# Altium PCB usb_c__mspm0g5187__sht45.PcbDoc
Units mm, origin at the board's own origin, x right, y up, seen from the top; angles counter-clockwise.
Board outline 68 x 40 mm, 2 copper layers (Top, Bottom), stack 0 mm thick; 35 components, 31 nets, 176 pads, 52 vias.
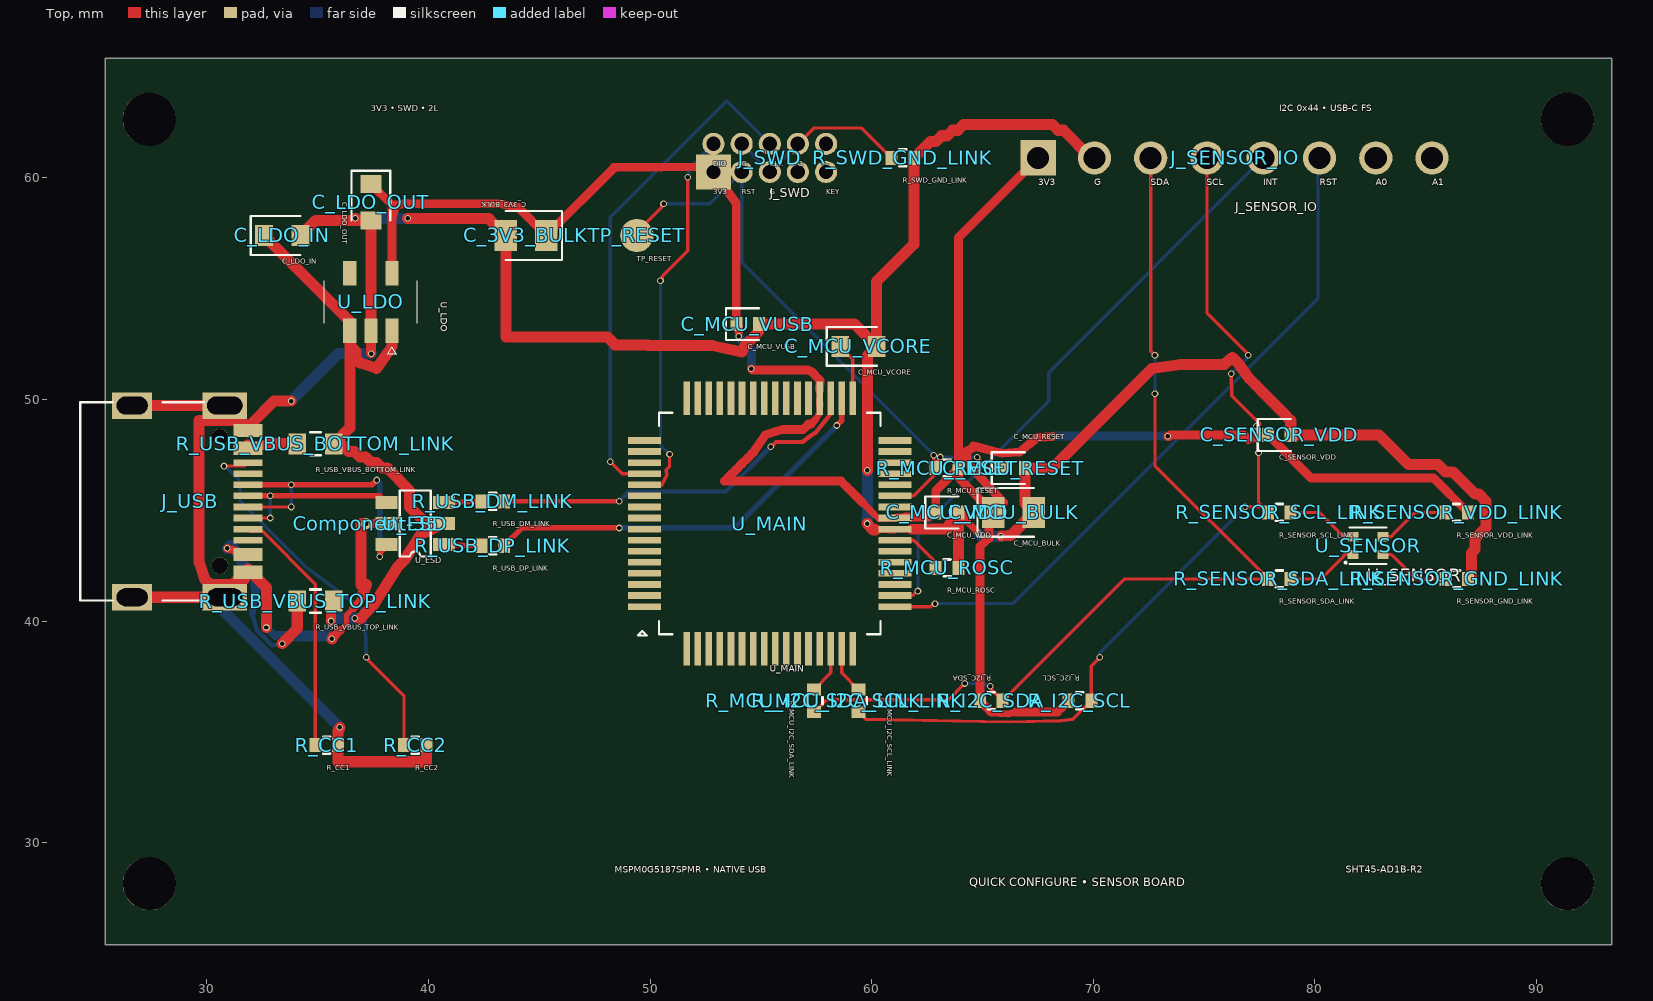
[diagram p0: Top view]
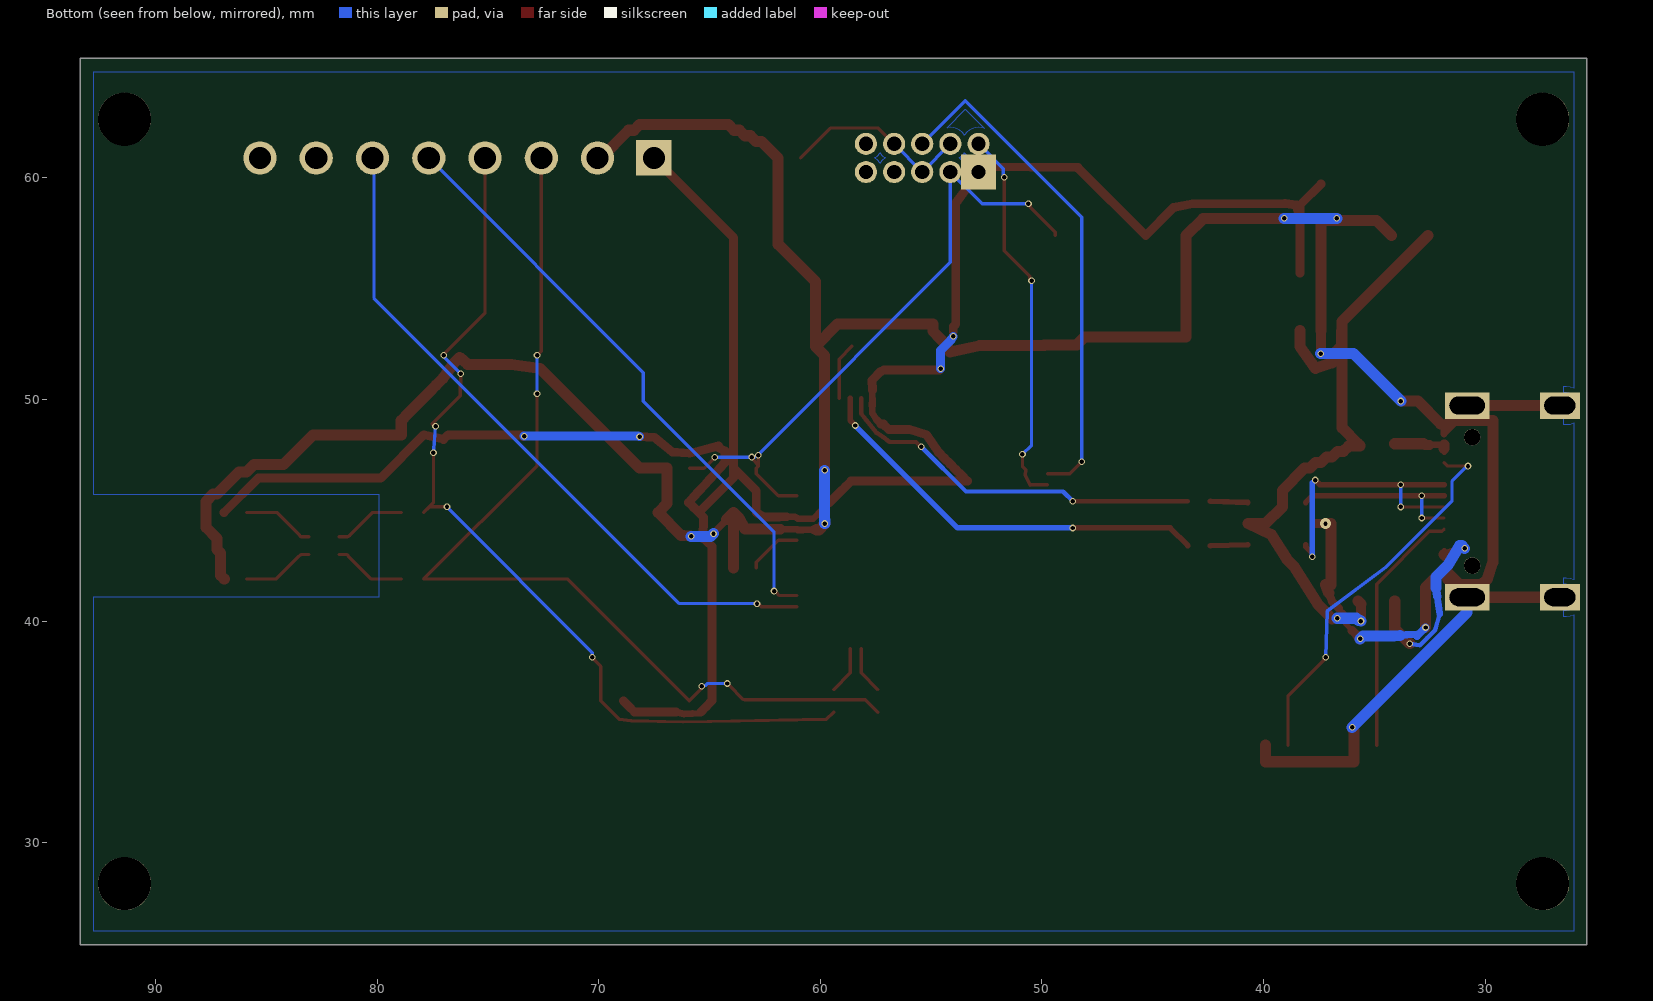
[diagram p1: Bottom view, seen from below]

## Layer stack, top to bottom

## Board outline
25.4,65.4 93.4,65.4 93.4,25.4 25.4,25.4

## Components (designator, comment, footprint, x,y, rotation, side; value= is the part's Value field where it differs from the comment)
C_3V3_BULK "" TSCIRCUIT-2.8500x1.4000mm 44.4,57.4 r180 top
C_LDO_IN "" TSCIRCUIT-2.4500x0.9500mm 33.4,57.4 r0 top
C_LDO_OUT "" TSCIRCUIT-0.9500x2.4500mm 37.4,58.9 r270 top
C_MCU_BULK "" TSCIRCUIT-2.8500x1.4000mm 66.4,44.9 r0 top
C_MCU_RESET "" TSCIRCUIT-1.5600x0.6400mm 66.4,46.9 r0 top
C_MCU_VCORE "" TSCIRCUIT-2.4500x0.9500mm 59.4,52.4 r0 top
C_MCU_VDD "" TSCIRCUIT-1.5600x0.6400mm 63.4,44.9 r0 top
C_MCU_VUSB "" TSCIRCUIT-1.5600x0.6400mm 54.4,53.4 r0 top
C_SENSOR_VDD "" TSCIRCUIT-1.5600x0.6400mm 78.4,48.4 r0 top
Component-35 "" TSCIRCUIT-0.5000x0.5000mm 37.2,44.4 r0 top
J_SENSOR_IO "" TSCIRCUIT-19.2800x1.5000mm 76.4,60.9 r0 top
J_SWD "" TSCIRCUIT-6.0800x2.2700mm 55.4,60.9 r0 top
J_USB "" TSCIRCUIT-6.7732x9.8502mm 29.112,45.4 r90 top
R_CC1 "" TSCIRCUIT-1.5600x0.6400mm 35.4,34.4 r0 top
R_CC2 "" TSCIRCUIT-1.5600x0.6400mm 39.4,34.4 r0 top
R_I2C_SCL "" TSCIRCUIT-1.5600x0.6400mm 69.4,36.4 r180 top
R_I2C_SDA "" TSCIRCUIT-1.5600x0.6400mm 65.4,36.4 r180 top
R_MCU_I2C_SCL_LINK "" TSCIRCUIT-0.6400x1.5600mm 59.4,36.4 r270 top
R_MCU_I2C_SDA_LINK "" TSCIRCUIT-0.6400x1.5600mm 57.4,36.4 r270 top
R_MCU_RESET "" TSCIRCUIT-1.5600x0.6400mm 63.4,46.9 r0 top
R_MCU_ROSC "" TSCIRCUIT-1.5600x0.6400mm 63.4,42.4 r0 top
R_SENSOR_GND_LINK "" TSCIRCUIT-1.5600x0.6400mm 86.4,41.9 r0 top
R_SENSOR_SCL_LINK "" TSCIRCUIT-1.5600x0.6400mm 78.4,44.9 r0 top
R_SENSOR_SDA_LINK "" TSCIRCUIT-1.5600x0.6400mm 78.4,41.9 r0 top
R_SENSOR_VDD_LINK "" TSCIRCUIT-1.5600x0.6400mm 86.4,44.9 r0 top
R_SWD_GND_LINK "" TSCIRCUIT-1.5600x0.6400mm 61.4,60.9 r0 top
R_USB_DM_LINK "" TSCIRCUIT-1.5600x0.6400mm 42.9,45.4 r0 top
R_USB_DP_LINK "" TSCIRCUIT-1.5600x0.6400mm 42.9,43.4 r0 top
R_USB_VBUS_BOTTOM_LINK "" TSCIRCUIT-2.4500x0.9500mm 34.9,48 r0 top
R_USB_VBUS_TOP_LINK "" TSCIRCUIT-2.4500x0.9500mm 34.9,40.9 r0 top
TP_RESET "" TSCIRCUIT-1.5000x1.5000mm 49.4,57.4 r0 top
U_ESD "" TSCIRCUIT-3.6000x2.5000mm 39.4,44.4 r0 top
U_LDO "" TSCIRCUIT-2.5000x3.7000mm 37.4,54.4 r270 top
U_MAIN "" TSCIRCUIT-12.8000x12.8000mm 55.4,44.4 r0 top
U_SENSOR "" TSCIRCUIT-1.8598x1.2201mm 82.4,43.4 r0 top

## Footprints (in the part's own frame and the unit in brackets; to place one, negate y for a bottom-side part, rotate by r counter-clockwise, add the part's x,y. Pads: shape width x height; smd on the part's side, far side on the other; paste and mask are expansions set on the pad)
TSCIRCUIT-0.5000x0.5000mm [mm]
TSCIRCUIT-0.6400x1.5600mm [mm]
  rect 0.54x0.64 smd: 1(-0.51,0) 2(0.51,0)
  silkscreen extent -0.15,-0.38 0.15,0.38
TSCIRCUIT-0.9500x2.4500mm [mm]
  rect 0.8x0.95 smd: 1(-0.825,0) 2(0.825,0)
  silkscreen extent -1.43,-0.87 0.82,0.88
TSCIRCUIT-1.5000x1.5000mm [mm]
  round 1.5 smd: 1(0,0)
TSCIRCUIT-1.5600x0.6400mm [mm]
  rect 0.54x0.64 smd: 1(-0.51,0) 2(0.51,0)
  silkscreen extent -0.98,-0.72 0.51,0.72
TSCIRCUIT-1.8598x1.2201mm [mm]
  rect 0.505x0.42 smd: 1(-0.677,-0.4) 2(-0.677,0.4) 3(0.677,0.4) 4(0.677,-0.4)
  silkscreen extent -1.05,-0.83 0.83,0.83
TSCIRCUIT-2.4500x0.9500mm [mm]
  rect 0.8x0.95 smd: 1(-0.825,0) 2(0.825,0)
  silkscreen extent -1.42,-0.87 0.82,0.87
TSCIRCUIT-2.5000x3.7000mm [mm]
  rect 1.1x0.6 smd: 1(1.3,0.95) 2(1.3,0) 3(1.3,-0.95) 4(-1.3,-0.95) 5(-1.3,0.95)
  silkscreen extent -0.95,-2.1 2.35,2.1
TSCIRCUIT-2.8500x1.4000mm [mm]
  rect 1.025x1.4 smd: 1(-0.913,0) 2(0.913,0)
  silkscreen extent -1.63,-1.1 0.91,1.1
TSCIRCUIT-3.6000x2.5000mm [mm]
  rect 1x0.6 smd: 1(-1.3,-0.95) 2(-1.3,0) 3(-1.3,0.95) 4(1.3,0.95) 5(1.3,0) 6(1.3,-0.95)
  silkscreen extent -0.7,-1.49 0.7,1.49
TSCIRCUIT-6.0800x2.2700mm [mm]
  rect 1.6x1.6 hole 0.65: 1(-2.54,-0.635)
  round 1 hole 0.65: 2(-2.54,0.635) 3(-1.27,0.635) 4(0,0.635) 5(1.27,0.635) 6(2.54,0.635) 7(2.54,-0.635) 8(1.27,-0.635) 9(0,-0.635) 10(-1.27,-0.635)
TSCIRCUIT-6.7732x9.8502mm [mm]
  rect 0.3x1.3 smd: 1(-3.35,-2.737) 2(-3.05,-2.737) 3(-2.55,-2.737) 4(-2.25,-2.737) 5(-1.75,-2.737) 6(-1.25,-2.737) 7(-0.75,-2.737) 8(-0.25,-2.737) 9(0.25,-2.737) 10(0.75,-2.737) 11(1.25,-2.737) 12(1.75,-2.737) 13(2.55,-2.737) 14(2.25,-2.737) 15(3.35,-2.737) 16(3.05,-2.737)
  rect 1.2x2 hole 0.8 slot 1.6 at 90 deg: 17(-4.325,-1.693) 18(4.325,-1.693)
  rect 1.2x1.8 hole 0.8 slot 1.4 at 90 deg: 19(4.325,2.487) 20(-4.325,2.487)
  round 0.75 hole 0.75 unplated: NPTH-1(-2.9,-1.468) NPTH-2(2.9,-1.468)
  silkscreen extent -4.47,-0.75 4.47,4.83
TSCIRCUIT-12.8000x12.8000mm [mm]
  rect 1.5x0.3 smd: 1(-5.65,-3.75) 2(-5.65,-3.25) 3(-5.65,-2.75) 4(-5.65,-2.25) 5(-5.65,-1.75) 6(-5.65,-1.25) 7(-5.65,-0.75) 8(-5.65,-0.25) 9(-5.65,0.25) 10(-5.65,0.75) 11(-5.65,1.25) 12(-5.65,1.75) 13(-5.65,2.25) 14(-5.65,2.75) 15(-5.65,3.25) 16(-5.65,3.75) 33(5.65,3.75) 34(5.65,3.25) 35(5.65,2.75) 36(5.65,2.25) 37(5.65,1.75) 38(5.65,1.25) 39(5.65,0.75) 40(5.65,0.25) 41(5.65,-0.25) 42(5.65,-0.75) 43(5.65,-1.25) 44(5.65,-1.75) 45(5.65,-2.25) 46(5.65,-2.75) 47(5.65,-3.25) 48(5.65,-3.75)
  rect 0.3x1.5 smd: 17(-3.75,5.65) 18(-3.25,5.65) 19(-2.75,5.65) 20(-2.25,5.65) 21(-1.75,5.65) 22(-1.25,5.65) 23(-0.75,5.65) 24(-0.25,5.65) 25(0.25,5.65) 26(0.75,5.65) 27(1.25,5.65) 28(1.75,5.65) 29(2.25,5.65) 30(2.75,5.65) 31(3.25,5.65) 32(3.75,5.65) 49(3.75,-5.65) 50(3.25,-5.65) 51(2.75,-5.65) 52(2.25,-5.65) 53(1.75,-5.65) 54(1.25,-5.65) 55(0.75,-5.65) 56(0.25,-5.65) 57(-0.25,-5.65) 58(-0.75,-5.65) 59(-1.25,-5.65) 60(-1.75,-5.65) 61(-2.25,-5.65) 62(-2.75,-5.65) 63(-3.25,-5.65) 64(-3.75,-5.65)
  silkscreen extent -5.95,-5.05 5,5
TSCIRCUIT-19.2800x1.5000mm [mm]
  rect 1.6x1.6 hole 1: 1(-8.89,0)
  round 1.5 hole 1: 2(-6.35,0) 3(-3.81,0) 4(-1.27,0) 5(1.27,0) 6(3.81,0) 7(6.35,0) 8(8.89,0)

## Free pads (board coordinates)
  round 2.4 hole 2.4 unplated: NPTH-3(27.4,28.15) NPTH-4(91.4,28.15) NPTH-5(27.4,62.65) NPTH-6(91.4,62.65)

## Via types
v1: diameter 0.3, hole 0.2, Top to Bottom, 51 vias
v2: diameter 0.5, hole 0.2, Top to Bottom, 1 vias

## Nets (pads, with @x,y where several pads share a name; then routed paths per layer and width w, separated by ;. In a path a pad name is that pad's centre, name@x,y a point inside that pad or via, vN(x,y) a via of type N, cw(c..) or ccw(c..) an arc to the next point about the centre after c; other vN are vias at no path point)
".J_SWD > .pin2 to .U_MAIN > .pin12": J_SWD.2 U_MAIN.12 | length 17.4
  Top w0.15: U_MAIN.12 50.491,46.15 50.537,46.135 50.744,46.57 50.734,46.838 50.877,46.981 v1(50.877,47.526) ; v1(50.467,55.354) 50.542,55.429 50.542,55.563 51.697,56.718 v1(51.697,60.03)
  Bottom w0.15: v1(50.467,55.354) 50.467,47.934 v1(50.877,47.526) ; v1(51.697,60.03) 51.741,60.128 51.741,60.248 51.741,60.416 J_SWD.2
".J_SWD > .pin4 to .U_MAIN > .pin13": J_SWD.4 U_MAIN.13 | length 23
  Top w0.15: v1(48.2,47.185) 48.216,47.169 48.735,46.65 U_MAIN.13
  Bottom w0.15: v1(48.2,47.185) 48.2,58.223 53.456,63.479 J_SWD.4
".U_MAIN > .pin42 to .R_MCU_ROSC > .pin1": R_MCU_ROSC.1 U_MAIN.42 | length 2.5
  Top w0.15: U_MAIN.42 61.888,43.65 62.889,42.649 62.889,42.401 R_MCU_ROSC.1
GND: C_3V3_BULK.2 C_LDO_IN.2 C_LDO_OUT.2 C_MCU_BULK.2 C_MCU_RESET.2 C_MCU_VCORE.2 C_MCU_VDD.2 C_MCU_VUSB.2 C_SENSOR_VDD.2 J_SENSOR_IO.2 J_USB.1 J_USB.2 J_USB.15 J_USB.16 J_USB.17 J_USB.18 J_USB.19 J_USB.20 R_CC1.2 R_CC2.2 R_MCU_ROSC.2 R_SENSOR_GND_LINK.2 R_SWD_GND_LINK.2 U_ESD.2 U_LDO.2 U_MAIN.41 | length 168.3
  Top w0.225: 35.997,39.573 36.297,39.872 36.297,40.274 36.598,40.575
  Top w0.275: 31.241,49.058 31.545,48.754 J_USB.16 ; J_USB.1@31.624,42.125 J_USB.2 J_USB.1@32.128,42.071
  Top w0.3: J_USB.1@31.699,41.9 J_USB.1 J_USB.1@31.849,42.2 ; J_USB.15@31.699,48.9 J_USB.15 ; J_USB.16@31.849,48.6 J_USB.15 ; J_USB.15@31.999,48.9 J_USB.15 ; 60.3,44.12 60.425,44.12 60.55,44.12 60.675,44.12 60.796,44.111 61.011,44.111 U_MAIN.41 61.144,44.15 61.238,44.15 61.331,44.15 61.425,44.15 61.519,44.15 61.613,44.15 61.706,44.15 61.8,44.15
  Top w0.325: J_USB.16 J_USB.16@31.849,48.6 ; 64.229,44.581 64.525,44.264 v1(64.821,43.946)
  Top w0.375: 36.598,40.575 36.899,40.877 37.049,41.257
  Top w0.4: v1@35.697,39.273 35.997,39.573 ; 37.2,44.4 U_ESD.2@37.6,44.4 ; v1@37.4,52.1 v1(37.416,52.069) ; 60.175,44.12 60.3,44.12
  Top w0.45: v1@37.4,52.1 37.4,52.6 U_LDO.2 ; v1(65.827,43.819) v1@65.865,43.857
  Top w0.475: 61.8,44.15 62.253,44.15 62.707,44.15 ; v1@65.865,43.857 65.994,43.857 66.181,43.869
  Top w0.5: J_USB.20 J_USB.17 ; J_USB.19 J_USB.18 ; J_USB.17 30.874,41.075 31.474,41.675 31.699,41.9 ; J_USB.18 30.874,49.725 31.474,49.125 31.699,48.9 ; 31.241,49.058 29.65,49.058 29.65,42.65 29.9,41.9 30.15,41.65 31.149,41.65 31.399,41.9 J_USB.1@31.624,42.125 ; J_USB.1@31.849,42.2 J_USB.2 ; 31.999,48.9 33.028,49.929 v1(33.802,49.929) ; J_USB.1@32.128,42.071 32.406,41.793 32.685,41.514 32.685,41.063 32.685,40.612 32.685,40.161 v1(32.685,39.71) ; C_LDO_IN.2 34.9,58.075 C_LDO_OUT.2 ; v1(35.638,39.197) 35.697,39.256 v1@35.697,39.273 ; v1(36,35.2) 35.98,35.18 35.98,35.121 35.91,35.051 R_CC1.2 35.91,33.65 39.91,33.65 R_CC2.2 ; v1(36.694,58.171) 36.781,58.084 36.9,58.084 36.91,58.075 C_LDO_OUT.2 ; 37.049,41.257 37.2,41.638 36.95,41.638 36.95,44.4 37.2,44.4 ; U_LDO.2 C_LDO_OUT.2 ; v1(39.062,58.171) 42.716,58.171 C_3V3_BULK.2 43.488,52.811 48.075,52.811 48.428,52.458 48.916,52.454 49.404,52.451 49.893,52.447 50.381,52.444 50.87,52.44 51.358,52.437 51.846,52.434 52.335,52.43 52.823,52.427 54.15,52.15 54.288,52.416 54.599,52.749 54.91,53.082 C_MCU_VUSB.2 59.225,53.4 C_MCU_VCORE.2 ; v1(59.8,44.4) 60.05,44.12 60.175,44.12 ; v1(59.806,46.8) 59.81,46.804 59.81,46.822 59.81,51.985 C_MCU_VCORE.2 ; 62.707,44.15 63.4,44.15 63.66,44.65 C_MCU_VDD.2 ; R_MCU_ROSC.2 C_MCU_VDD.2 ; 64.229,44.581 C_MCU_VDD.2 ; 66.181,43.869 66.281,43.869 C_MCU_BULK.2 66.91,45.303 C_MCU_RESET.2 68.15,46.9 72.65,51.4 73.94,51.573 74.434,51.577 74.928,51.581 75.422,51.584 75.916,51.588 76.275,51.9 76.525,51.65 77.035,50.958 77.348,50.64 77.661,50.323 77.973,50.006 78.286,49.688 78.598,49.371 78.911,49.054 78.911,48.727 C_SENSOR_VDD.2 79.408,48.4 79.906,48.4 80.405,48.4 80.903,48.4 81.401,48.4 81.899,48.4 82.398,48.4 82.896,48.4 82.9,48.4 84.233,47.067 85.567,47.067 85.9,46.733 86.233,46.733 87.233,45.733 87.4,45.733 87.733,45.4 87.733,44.233 87.233,43.733 87.233,43.233 87.067,43.067 87.067,42.067 86.9,41.9 R_SENSOR_GND_LINK.2 ; J_SENSOR_IO.2 69.9,60.9 68.65,62.15 68.4,62.15 68.15,62.4 64.15,62.4 63.9,62.15 63.65,62.15 63.4,61.9 63.15,61.9 62.9,61.65 62.65,61.65 62.65,61.64 62.579,61.569 62.244,61.234 R_SWD_GND_LINK.2 61.91,57.006 60.225,55.321 60.225,54.834 60.225,54.347 60.225,53.86 60.225,53.374 60.225,52.887 C_MCU_VCORE.2
  Bottom w0.312: 33.069,39.328 33.072,39.384 33.541,39.384
  Bottom w0.35: v1(32.685,39.71) 32.803,39.592 32.805,39.592 33.069,39.328 ; 33.541,39.384 33.83,39.356
  Bottom w0.5: J_USB.17 30.806,40.394 v1(36,35.2) ; v1(33.802,49.929) 35.942,52.069 v1(37.416,52.069) ; 33.83,39.356 34.119,39.328 34.582,39.328 35.044,39.328 35.507,39.328 v1(35.638,39.197) ; v1(36.694,58.171) v1(39.062,58.171) ; v1(59.8,44.4) 59.8,44.554 59.806,44.56 v1(59.806,46.8) ; v1(64.821,43.946) 64.949,43.819 v1(65.827,43.819)
MAIN_RESET: C_MCU_RESET.1 J_SWD.10 R_MCU_RESET.1 TP_RESET.1 U_MAIN.38 | length 29.7
  Top w0.15: TP_RESET.1 49.4,57.55 50.531,58.681 50.531,58.754 v1(50.607,58.83) ; U_MAIN.38 61.889,45.65 62.89,46.651 R_MCU_RESET.1 ; v1(62.8,47.485) R_MCU_RESET.1@62.8,46.99 ; v1(63.1,47.4) R_MCU_RESET.1@62.8,46.99 ; v1(64.759,47.387) v1@64.817,47.329 ; v1@64.817,47.328 65.245,46.9 C_MCU_RESET.1 ; R_MCU_RESET.1@62.8,46.99 R_MCU_RESET.1 ; R_MCU_RESET.1@62.8,46.99 R_MCU_RESET.1
  Bottom w0.15: v1(50.607,58.83) 52.695,58.83 J_SWD.10 54.13,56.188 62.736,47.582 62.736,47.549 v1(62.8,47.485) ; v1(63.1,47.4) 62.838,47.447 62.908,47.447 62.968,47.387 v1(64.759,47.387)
MCU_I2C_SCL_LOCAL: R_MCU_I2C_SCL_LINK.1 U_MAIN.50 | length 2.2
  Top w0.15: U_MAIN.50 58.65,37.66 R_MCU_I2C_SCL_LINK.1
MCU_I2C_SDA_LOCAL: R_MCU_I2C_SDA_LINK.1 U_MAIN.51 | length 2.2
  Top w0.15: R_MCU_I2C_SDA_LINK.1 58.15,37.66 U_MAIN.51
MSPM0_VCORE: C_MCU_VCORE.1 U_MAIN.32 | length 2.6
  Top w0.15: C_MCU_VCORE.1 59.15,51.825 U_MAIN.32
SENSOR_ADDR0: J_SENSOR_IO.7
SENSOR_ADDR1: J_SENSOR_IO.8
SENSOR_INT: J_SENSOR_IO.5 U_MAIN.47 | length 27.1
  Top w0.15: U_MAIN.47 61.846,41.15 61.99,41.294 62.027,41.294 v1(62.087,41.354)
  Bottom w0.15: v1(62.087,41.354) 62.087,44.012 67.985,49.91 67.985,51.215 J_SENSOR_IO.5
SENSOR_RESET: J_SENSOR_IO.6 U_MAIN.48 | length 31.2
  Top w0.15: U_MAIN.48 62.661,40.65 62.759,40.748 62.818,40.748 v1(62.858,40.788)
  Bottom w0.15: v1(62.858,40.788) 66.356,40.788 80.144,54.576 80.144,60.834 J_SENSOR_IO.6
SENSOR_SCL: J_SENSOR_IO.4 R_I2C_SCL.1 R_MCU_I2C_SCL_LINK.2 R_SENSOR_SCL_LINK.1 | length 41.7
  Top w0.15: R_MCU_I2C_SCL_LINK.2 59.724,35.566 66.195,35.444 68.539,35.498 69.076,35.566 R_I2C_SCL.1 69.91,37.952 70.227,38.269 70.227,38.303 v1(70.292,38.368) ; J_SENSOR_IO.4 75.13,53.903 77.019,52.014 v1(76.993,51.988) ; v1(76.232,51.163) 76.254,50.164 77.475,48.944 77.515,48.903 77.487,48.857 v1(77.364,48.787) ; v1(76.849,45.158) 77.632,45.158 R_SENSOR_SCL_LINK.1 77.46,45.33 v1(77.46,47.59)
  Bottom w0.15: v1(70.292,38.368) 70.292,38.578 76.796,45.082 76.796,45.105 v1(76.849,45.158) ; v1(76.232,51.163) 76.332,51.264 76.993,51.925 v1(76.993,51.988) ; v1(77.364,48.787) 77.451,47.765 77.451,47.599 v1(77.46,47.59)
SENSOR_SDA: J_SENSOR_IO.3 R_I2C_SDA.1 R_MCU_I2C_SDA_LINK.2 R_SENSOR_SDA_LINK.1 | length 45
  Top w0.15: R_MCU_I2C_SDA_LINK.2 57.967,36.448 63.415,36.453 63.467,36.457 64.137,37.127 64.147,37.127 v1(64.202,37.182) ; v1(65.355,37.053) 65.28,37.043 R_I2C_SDA.1 71.41,41.9 R_SENSOR_SDA_LINK.1 72.783,47.007 v1(72.783,50.25) ; J_SENSOR_IO.3 72.59,52.173 72.783,51.98 v1(72.783,51.991)
  Bottom w0.15: v1(64.202,37.182) 65.078,37.182 65.165,37.095 65.225,37.095 v1(65.355,37.053) ; v1(72.783,50.25) 72.783,50.473 v1(72.783,51.991)
SHT_GND_LOCAL: R_SENSOR_GND_LINK.1 U_SENSOR.4 | length 3.3
  Top w0.15: U_SENSOR.4 83.44,43 83.551,42.893 84.544,41.9 R_SENSOR_GND_LINK.1
SHT_SCL_LOCAL: R_SENSOR_SCL_LINK.2 U_SENSOR.2 | length 3.3
  Top w0.15: R_SENSOR_SCL_LINK.2 80.201,44.9 81.232,43.868 81.36,43.8 U_SENSOR.2
SHT_SDA_LOCAL: R_SENSOR_SDA_LINK.2 U_SENSOR.1 | length 3.3
  Top w0.15: R_SENSOR_SDA_LINK.2 80.281,41.9 81.256,42.875 81.36,43 U_SENSOR.1
SHT_VDD_LOCAL: R_SENSOR_VDD_LINK.1 U_SENSOR.3 | length 3.3
  Top w0.15: U_SENSOR.3 83.44,43.8 83.546,43.92 84.526,44.9 R_SENSOR_VDD_LINK.1
swd-ground-1-to-2: J_SWD.3 J_SWD.5 J_SWD.9 R_SWD_GND_LINK.1 | length 8.7
  Top w0.15: J_SWD.5 57.382,62.247 59.375,62.247 59.543,62.247 R_SWD_GND_LINK.1
  Bottom w0.15: J_SWD.3 J_SWD.9 J_SWD.5
usb-dm-device: R_USB_DM_LINK.1 U_ESD.4 | length 1.7
  Top w0.25: U_ESD.4 R_USB_DM_LINK.1
usb-dm-mcu: R_USB_DM_LINK.2 U_MAIN.30 | length 17.1
  Top w0.2: R_USB_DM_LINK.2 v1(48.6,45.4) ; v1(55.443,47.863) 55.445,47.861 55.464,47.861 55.682,48.079 56.872,48.079 57.158,48.304 57.484,48.503 57.93,49.065 58.15,49.357 U_MAIN.30
  Bottom w0.2: v1(48.6,45.4) 49.032,45.832 49.032,45.846 53.426,45.846 v1(55.443,47.863)
usb-dm-port-tie: J_USB.7 J_USB.9 U_ESD.3 | length 9.4
  Top w0.15: J_USB.7 v1(32.85,44.65) ; J_USB.9 v1(32.85,45.65)
  Top w0.25: J_USB.9 37.8,45.65 U_ESD.3
  Bottom w0.15: v1(32.85,44.65) v1(32.85,45.65)
usb-dp-device: R_USB_DP_LINK.1 U_ESD.6 | length 1.7
  Top w0.25: U_ESD.6 R_USB_DP_LINK.1
usb-dp-mcu: R_USB_DP_LINK.2 U_MAIN.31 | length 18.6
  Top w0.25: R_USB_DP_LINK.2 44.21,44.2 v1(48.6,44.2) ; v1(58.427,48.825) 58.466,48.864 58.466,48.876 58.65,49.06 U_MAIN.31
  Bottom w0.25: v1(48.6,44.2) 53.802,44.2 v1(58.427,48.825)
usb-dp-port-tie: J_USB.8 J_USB.10 U_ESD.1 | length 15
  Top w0.15: J_USB.8 v1(33.8,45.15) ; J_USB.10 v1(33.8,46.15)
  Top w0.25: J_USB.10 37.455,46.15 v1(37.668,46.363) ; v1(37.8,42.9) 37.808,42.908 37.808,43.071 38.1,43.363 U_ESD.1
  Bottom w0.15: v1(33.8,45.15) v1(33.8,46.15)
  Bottom w0.25: v1(37.668,46.363) 37.683,46.348 37.8,46.231 v1(37.8,42.9)
USB_CC1: J_USB.6 R_CC1.1 | length 11.3
  Top w0.15: J_USB.6 31.95,44.049 32.515,44.053 34.89,41.669 R_CC1.1
USB_CC2: J_USB.12 R_CC2.1 | length 17.3
  Top w0.15: v1(30.77,46.994) 31.693,46.994 J_USB.12 ; v1(37.193,38.361) 37.28,38.274 37.28,38.233 38.89,36.622 R_CC2.1
  Bottom w0.15: v1(30.77,46.994) 30.855,46.909 30.884,46.909 31.493,46.3 31.493,45.413 34.481,42.424 37.125,40.45 v1(37.193,38.361)
USB_VBUS_BOTTOM_LOCAL: J_USB.13 J_USB.14 R_USB_VBUS_BOTTOM_LINK.1 | length 2.5
  Top w0.3: J_USB.14 J_USB.14@31.849,47.8 ; J_USB.13 J_USB.13@32.499,47.95
  Top w0.437: 32.72,47.95 32.769,48
  Top w0.45: 32.499,47.95 32.72,47.95
  Top w0.475: J_USB.13@31.849,47.8 J_USB.13
  Top w0.5: 32.769,48 33.205,48 33.64,48 R_USB_VBUS_BOTTOM_LINK.1
USB_VBUS_TOP_LOCAL: J_USB.3 J_USB.4 R_USB_VBUS_TOP_LINK.1 | length 9.5
  Top w0.275: J_USB.4@31.634,43.066 J_USB.3
  Top w0.3: J_USB.3 31.849,43 J_USB.4
  Top w0.375: v1(30.921,43.281) 31.277,43.173 J_USB.4@31.634,43.066
  Top w0.5: v1(33.399,38.978) 34.075,39.654 R_USB_VBUS_TOP_LINK.1
  Bottom w0.2: 32.044,40.323 32.147,39.962 32.25,39.6 32.6,39.25 32.95,38.9 v1(33.399,38.978)
  Bottom w0.312: 32.044,40.323 32.1,40.713 32.156,41.104
  Bottom w0.375: 32.156,41.104 32.213,41.494
  Bottom w0.5: v1(30.921,43.281) 31.04,43.4 31.15,43.4 31.691,42.515 32.213,41.993 32.213,41.494
VBUS5: C_LDO_IN.1 R_USB_VBUS_BOTTOM_LINK.2 R_USB_VBUS_TOP_LINK.2 U_ESD.5 U_LDO.1 U_LDO.3 | length 30.9
  Top w0.3: v1(36.671,40.127) v1@36.7,40.1
  Top w0.325: v1@36.7,40.1 36.9,40.1
  Top w0.45: v1(35.6,40) 35.6,40.388 R_USB_VBUS_TOP_LINK.2@35.6,40.775
  Top w0.5: C_LDO_IN.1 36.45,53.525 U_LDO.3 ; R_USB_VBUS_TOP_LINK.2@35.6,40.775 R_USB_VBUS_TOP_LINK.2 ; 36.9,40.1 37.2,40.4 37.5,40.7 38.641,42.49 38.959,42.808 39.65,43.9 U_ESD.5 39.9,44.4 39.15,45.15 39.15,45.9 38.15,46.9 37.9,46.9 37.65,47.15 37.4,47.15 37.15,47.4 36.9,47.4 36.65,47.65 36.4,47.65 36.15,47.9 35.65,47.9 35.65,47.925 R_USB_VBUS_BOTTOM_LINK.2 36.45,48.725 U_LDO.3 ; U_LDO.1 38.35,52.742 38.351,52.383 37.65,51.4 36.9,51.65 36.729,51.821 36.729,52.16 36.473,52.434 36.473,53.077 U_LDO.3
  Bottom w0.5: v1(35.6,40) 35.628,40.028 35.714,40.028 35.813,40.127 36.242,40.127 v1(36.671,40.127)
VCC_3V3: C_3V3_BULK.1 C_LDO_OUT.1 C_MCU_BULK.1 C_MCU_VDD.1 C_MCU_VUSB.1 C_SENSOR_VDD.1 J_SENSOR_IO.1 J_SWD.1 R_I2C_SCL.2 R_I2C_SDA.2 R_MCU_RESET.2 R_SENSOR_VDD_LINK.2 U_LDO.5 U_MAIN.29 U_MAIN.40 | length 116.1
  Top w0.3: v1(54,52.846) 54,53.068 ; 57.45,49.075 57.661,49.388 U_MAIN.29@57.655,49.719 ; U_MAIN.29 U_MAIN.29@57.65,50.424 ; 60.072,44.86 60.315,44.617 60.666,44.617 61.017,44.617 U_MAIN.40 ; 65.393,35.888 65.4,35.838 65.775,35.819
  Top w0.306: U_MAIN.40 61.162,44.705 U_MAIN.40@61.509,44.704
  Top w0.312: 59.83,45.103 60.072,44.86 ; 65.775,35.819 66.15,35.8
  Top w0.325: U_MAIN.29 U_MAIN.29@57.655,49.719 ; 59.587,45.346 59.83,45.103 ; 66.15,35.8 66.516,35.891
  Top w0.337: 57.275,48.9 57.45,49.075
  Top w0.387: U_MAIN.40@61.509,44.704 61.856,44.703
  Top w0.4: C_LDO_OUT.1 38.35,58.775 U_LDO.5 38.342,58.108 38.51,58.772 39.025,58.846 43.199,58.831 44.063,58.66 C_3V3_BULK.1 48.374,60.461 48.441,60.473 52.664,60.502 J_SWD.1 53.89,58.846 53.89,58.457 53.89,58.068 53.89,57.679 53.89,57.29 53.89,56.901 53.89,56.512 53.89,56.123 53.89,55.734 53.89,55.345 53.89,54.956 53.89,54.567 53.89,54.178 53.89,53.789 C_MCU_VUSB.1 54,53.29 54,53.068 ; v1(54.572,51.384) 54.622,51.334 54.627,51.329 54.983,51.329 55.339,51.329 55.695,51.329 56.051,51.329 56.407,51.329 56.763,51.329 57.119,51.329 57.267,51.267 57.667,50.867 U_MAIN.29@57.65,50.424 ; 57.275,48.9 57.156,48.891 56.903,48.643 56.601,48.644 56.299,48.645 55.997,48.646 55.2,48.4 54.66,47.612 54.401,47.353 54.142,47.094 53.883,46.835 53.624,46.576 53.365,46.317 53.74,46.317 54.115,46.317 54.49,46.317 54.865,46.317 55.24,46.317 55.615,46.317 55.99,46.317 56.365,46.317 56.74,46.317 57.115,46.317 57.491,46.317 57.866,46.317 58.241,46.317 58.616,46.317 58.859,46.074 59.101,45.831 59.344,45.588 59.587,45.346 ; 61.856,44.703 62.203,44.701 62.55,44.7 C_MCU_VDD.1 62.89,45.88 R_MCU_RESET.2 ; 65.393,35.888 65.142,36.144 R_I2C_SDA.2 64.887,43.372 65.293,43.731 65.264,44.671 C_MCU_BULK.1 ; 66.516,35.891 66.89,35.891 67.264,35.892 67.638,35.893 68.012,35.894 68.387,35.894 68.638,36.147 R_I2C_SCL.2 ; J_SENSOR_IO.1 63.91,57.3 R_MCU_RESET.2 ; v1(68.157,48.324) 67.834,48.31 67.51,48.297 67.233,48.073 66.955,47.848 66.678,47.624 65.91,47.57 65.595,47.64 64.6,47.9 64.65,47.85 64.3,47.675 64.3,47.413 64.3,47.15 64.535,46.894 64.77,46.637 65.004,46.381 65.239,46.125 65.474,45.869 65.709,45.612 65.944,45.356 65.716,45.128 C_MCU_BULK.1 ; v1(73.365,48.347) 73.376,48.336 73.417,48.336 73.481,48.4 73.848,48.4 74.215,48.4 74.583,48.4 74.95,48.4 75.318,48.4 75.685,48.4 76.053,48.4 76.42,48.4 76.788,48.4 77,48.2 C_SENSOR_VDD.1 79.842,46.448 85.301,46.448 85.362,46.448 R_SENSOR_VDD_LINK.2 ; R_MCU_RESET.2 63.91,46.478 C_MCU_BULK.1
  Bottom w0.4: v1(54,52.846) 54.099,52.701 54.099,52.687 54.335,52.45 54.572,52.213 54.572,51.937 54.572,51.66 v1(54.572,51.384) ; v1(68.157,48.324) 68.234,48.347 68.365,48.347 68.75,48.347 69.135,48.347 69.519,48.347 69.904,48.347 70.288,48.347 70.673,48.347 71.058,48.347 71.442,48.347 71.827,48.347 72.211,48.347 72.596,48.347 72.98,48.347 v1(73.365,48.347)
pads on no net: J_SWD.6 J_SWD.7 J_SWD.8 J_USB.5 J_USB.11 J_USB.NPTH-1 J_USB.NPTH-2 U_LDO.4 U_MAIN.1 U_MAIN.2 U_MAIN.3 U_MAIN.4 U_MAIN.5 U_MAIN.6 U_MAIN.7 U_MAIN.8 U_MAIN.9 U_MAIN.10 U_MAIN.11 U_MAIN.14 U_MAIN.15 U_MAIN.16 U_MAIN.17 U_MAIN.18 U_MAIN.19 U_MAIN.20 U_MAIN.21 U_MAIN.22 U_MAIN.23 U_MAIN.24 U_MAIN.25 U_MAIN.26 U_MAIN.27 U_MAIN.28 U_MAIN.33 U_MAIN.34 U_MAIN.35 U_MAIN.36 U_MAIN.37 U_MAIN.39 U_MAIN.43 U_MAIN.44 U_MAIN.45 U_MAIN.46 U_MAIN.49 U_MAIN.52 U_MAIN.53 U_MAIN.54 U_MAIN.55 U_MAIN.56 U_MAIN.57 U_MAIN.58 U_MAIN.59 U_MAIN.60 U_MAIN.61 U_MAIN.62 U_MAIN.63 U_MAIN.64
copper on no net:
  other v2: 37.2,44.4

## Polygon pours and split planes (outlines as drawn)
GND on Bottom (solid): 92.8,64.8 26,64.8 26,50.51 26.001,50.51 26.16,50.559 26.326,50.575 26.476,50.575 26.476,50.325 26.326,50.325 26.209,50.314 26.096,50.279 26,50.228 26,49.222 26.096,49.171 26.209,49.137 26.326,49.125 26.476,49.125 26.476,48.875 26.326,48.875 26.16,48.891 26.001,48.94 26,48.94 26,41.86 26.001,41.86 26.16,41.909 26.326,41.925 26.476,41.925 26.476,41.675 26.326,41.675 26.209,41.663 26.096,41.629 26,41.578 26,40.572 26.096,40.521 26.209,40.486 26.326,40.475 26.476,40.475 26.476,40.225 26.326,40.225 26.16,40.241 26.001,40.29 26,40.29 26,26 92.8,26 92.8,41.1 80.2,41.1 79.9,41.1 79.9,41.4 79.9,45.1 79.9,45.7 80.5,45.7 92.8,45.7
GND on Bottom (solid): 53.456,63.09 52.603,62.237 52.714,62.271 52.86,62.285 53.006,62.271 53.147,62.228 53.277,62.159 53.39,62.065 53.484,61.952 53.495,61.93 53.506,61.952 53.6,62.065 53.713,62.159 53.843,62.228 53.984,62.271 54.13,62.285 54.275,62.271
GND on Bottom (solid): 53.495,61.14 53.484,61.118 53.399,61.015 53.591,61.015 53.506,61.118
GND on Bottom (solid): 53.61,60.996 53.61,60.804 53.713,60.889 53.735,60.9 53.713,60.911
GND on Bottom (solid): 57.305,61.14 57.294,61.118 57.2,61.005 57.087,60.911 57.065,60.9 57.087,60.889 57.2,60.795 57.294,60.682 57.305,60.66 57.316,60.682 57.41,60.795 57.523,60.889 57.545,60.9 57.523,60.911 57.41,61.005 57.316,61.118

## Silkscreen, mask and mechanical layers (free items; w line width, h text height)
Top Overlay:
  text "3V3 • SWD • 2L" at 37.4,62.9 h0.48
  text "I2C 0x44 • USB-C FS" at 78.4,62.9 h0.5
  text "MSPM0G5187SPMR • NATIVE USB" at 48.4,28.525 h0.52
  text "SHT45-AD1B-R2" at 81.4,28.525 h0.55
  text "QUICK CONFIGURE • SENSOR BOARD" at 64.4,27.9 h0.65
